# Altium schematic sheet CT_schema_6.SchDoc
size 266 x 267 mm
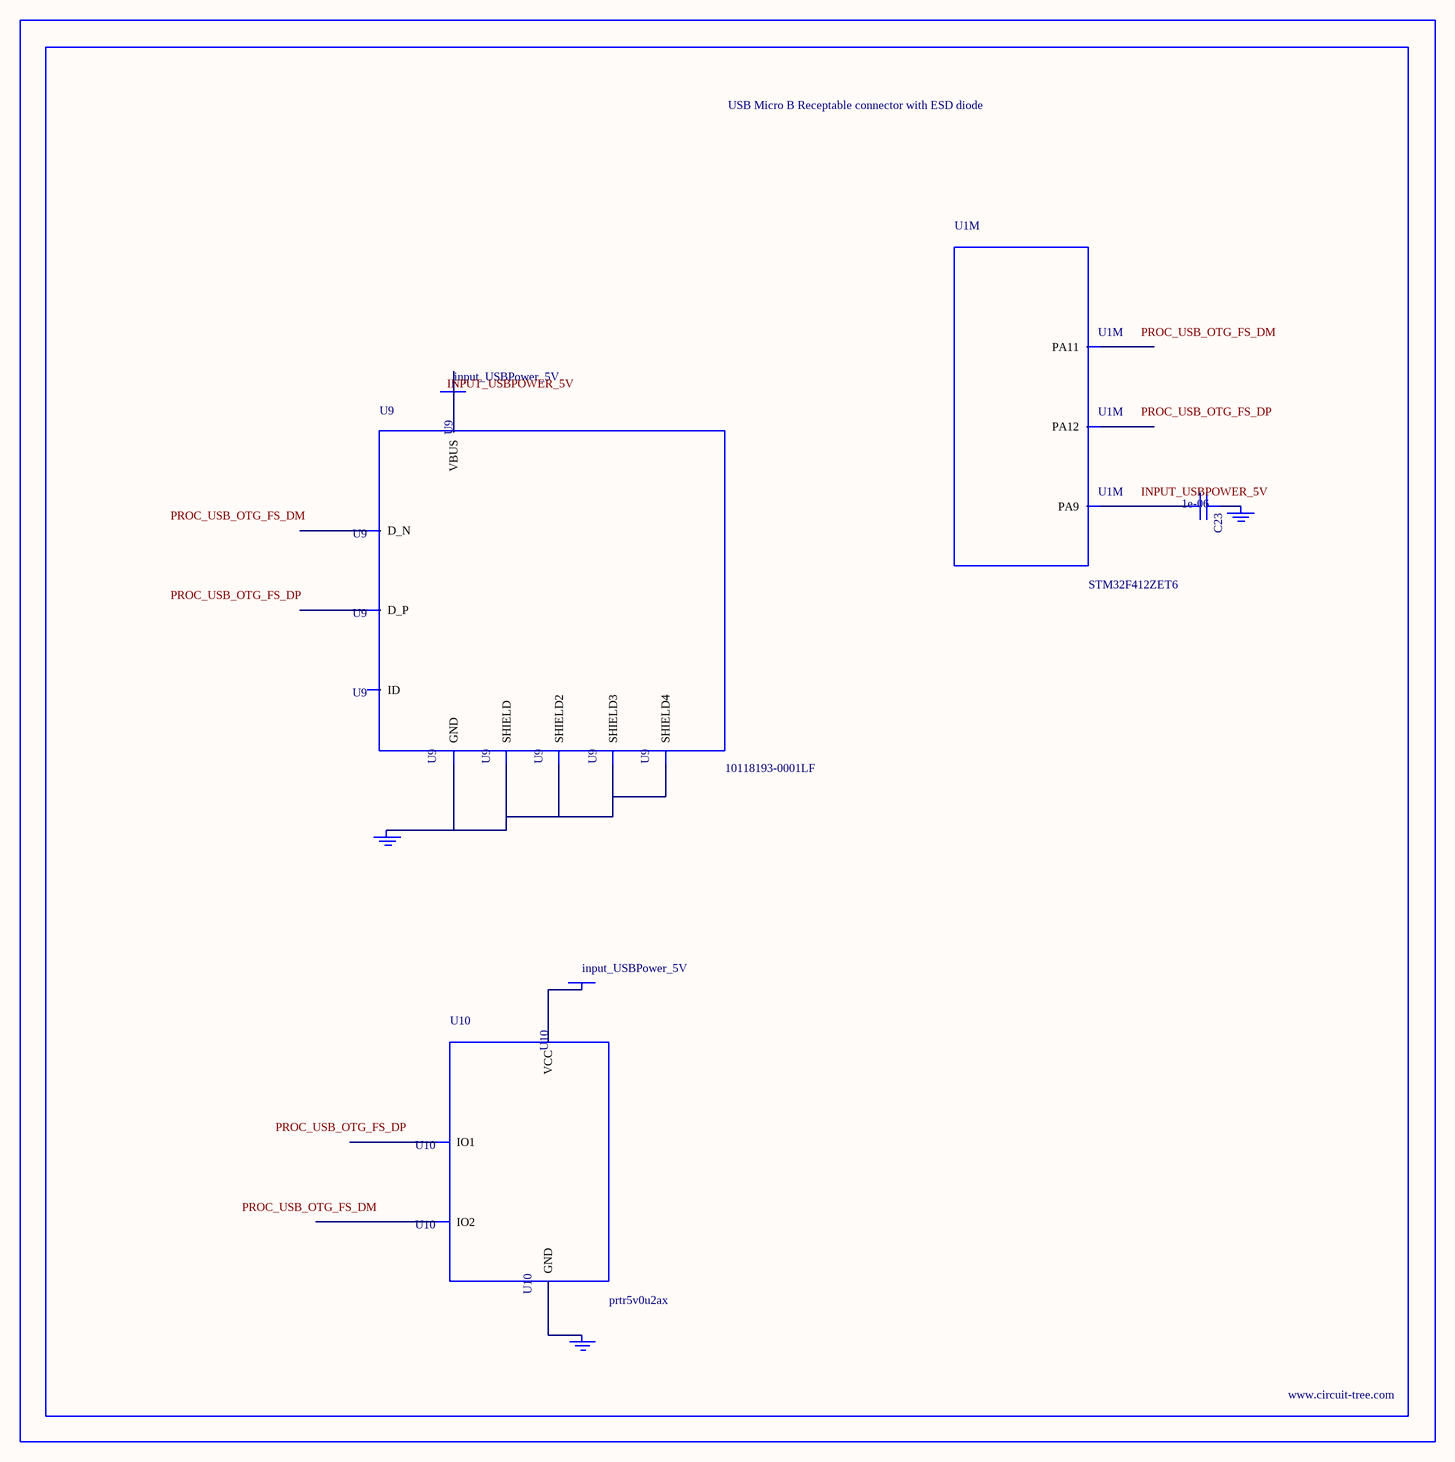
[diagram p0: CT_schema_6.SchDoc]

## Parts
BORDER5  (no value)
C23  1e-06  [C0603]
GND_INSTANCE_5_0  (no value)
GND_INSTANCE_5_1  (no value)
GND_INSTANCE_5_2  (no value)
POWER_INSTANCE_5_0  input_USBPower_5V
POWER_INSTANCE_5_1  input_USBPower_5V
U1  STM32F412ZET6  [LQFP144]  (part M of 13)
U9  10118193-0001LF  [FCI_10118193-0001LF]
U10  prtr5v0u2ax  [SOT143B]

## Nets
NetC23_1: C23.1 GND_INSTANCE_5_1.0(GND)
NetC23_2: C23.2 U1.101(PA9)
NetGND_INSTANCE_5_0_0: GND_INSTANCE_5_0.0(GND) U9.5(GND) U9.6(SHIELD) U9.7(SHIELD2) U9.8(SHIELD3) U9.9(SHIELD4)
NetGND_INSTANCE_5_2_0: GND_INSTANCE_5_2.0(GND) U10.1(GND)
NetPOWER_INSTANCE_5_0_0: POWER_INSTANCE_5_0.0(PWR) U9.1(VBUS)
NetPOWER_INSTANCE_5_1_0: POWER_INSTANCE_5_1.0(PWR) U10.4(VCC)

Not connected (* = marked no-connect by the designer): U1 103(PA11) 104(PA12); U9 2(D_N) 3(D_P) 4(ID); U10 2(IO1) 3(IO2)

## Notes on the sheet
- Labels drawn without touching a wire or pin: INPUT_USBPOWER_5V, PROC_USB_OTG_FS_DM, PROC_USB_OTG_FS_DP

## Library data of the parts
BORDER5 = BORDER_PAGE5
C23 = C0603C105K3RACTU
GND_INSTANCE_5_0-GND_INSTANCE_5_2 = GND
POWER_INSTANCE_5_0 POWER_INSTANCE_5_1 = PWR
